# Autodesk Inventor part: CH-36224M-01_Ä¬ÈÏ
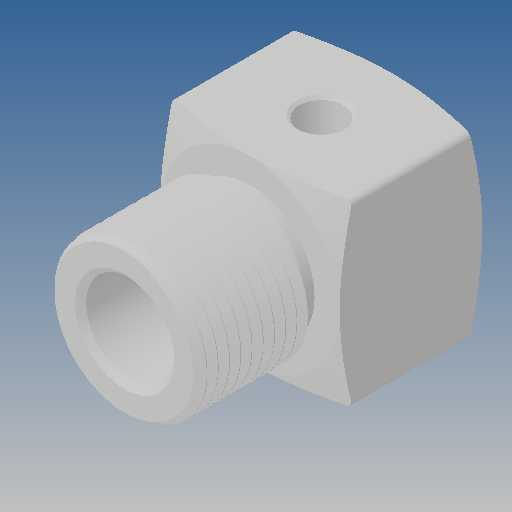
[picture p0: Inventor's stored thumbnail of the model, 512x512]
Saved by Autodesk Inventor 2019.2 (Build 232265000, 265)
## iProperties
Created: 2010-06
Part Number: CH-36224M-01_Ä¬ÈÏ
Material: Ogólny
Document SubType Name: Modeling
Designer: CADENGINEERING4
Density: 1 g/cm^3
Appearance: Domyślna
Author: CADENGINEERING4
Revision Number: ÈÎºÎ
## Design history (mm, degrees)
feature "NONE"
node "Bryła1"
